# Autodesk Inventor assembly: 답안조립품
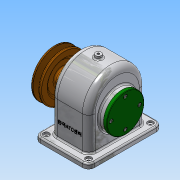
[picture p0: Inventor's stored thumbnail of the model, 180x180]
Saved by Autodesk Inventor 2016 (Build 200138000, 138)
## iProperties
Created: 2018-08
Part Number: 답안조립품
Material: 일반
Document SubType Name: Assembly
Designer: Administrator
Author: Administrator
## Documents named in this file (14)
- C:\Users\Administrator\Desktop\480811V1018\답안조립품.iam
- C:\Users\Administrator\Desktop\480811V1018\본체.ipt
- C:\Users\Administrator\Desktop\480811V1018\축.ipt
- C:\Users\Administrator\Desktop\480811V1018\베어링 6203.ipt
- C:\Users\Administrator\Desktop\480811V1018\키 6x6x22.ipt
- C:\Users\Administrator\Desktop\480811V1018\스퍼기어.ipt
- C:\Users\Administrator\Desktop\480811V1018\뒤커버.ipt
- C:\Users\Administrator\Desktop\480811V1018\부시.ipt
- C:\Users\Administrator\Desktop\480811V1018\앞커버.ipt
- C:\Users\Administrator\Desktop\480811V1018\키 5x5x18.ipt
- C:\Users\Administrator\Desktop\480811V1018\V-벨트풀리.ipt
- C:\Users\Administrator\Desktop\480811V1018\오일 실 28 40 8.ipt
- C:\Users\Administrator\Desktop\480811V1018\멈춤나사 M4.ipt
- C:\Users\Administrator\Desktop\480811V1018\볼트 M4.ipt
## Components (1 placed, 1 different names)
1. V-벨트풀리:1 — 플러쉬:1
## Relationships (1: Flush 1)
- 플러쉬:1 [Flush]: V-벨트풀리:1
